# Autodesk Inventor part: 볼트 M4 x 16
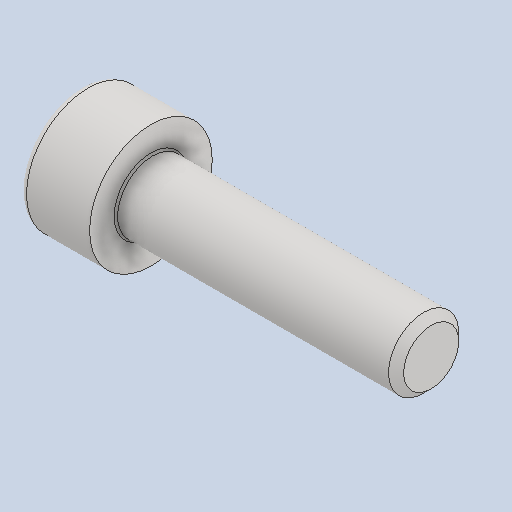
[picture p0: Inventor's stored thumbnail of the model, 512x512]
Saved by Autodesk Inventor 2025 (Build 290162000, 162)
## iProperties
Created: 2024-07
Part Number: 볼트 M4 x 16
Material: 스테인리스강
Description: 6각 소켓 머리 캡 나사
Document SubType Name: Modeling
Designer: Administrator
Density: 8.08 g/cm^3
Appearance: 기본값
Author: jhkim
Sending System: Autodesk Inventor 2025
Preprocessor: ST-DEVELOPER v20
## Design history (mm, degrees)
feature "Solid1"
node "솔리드1"
